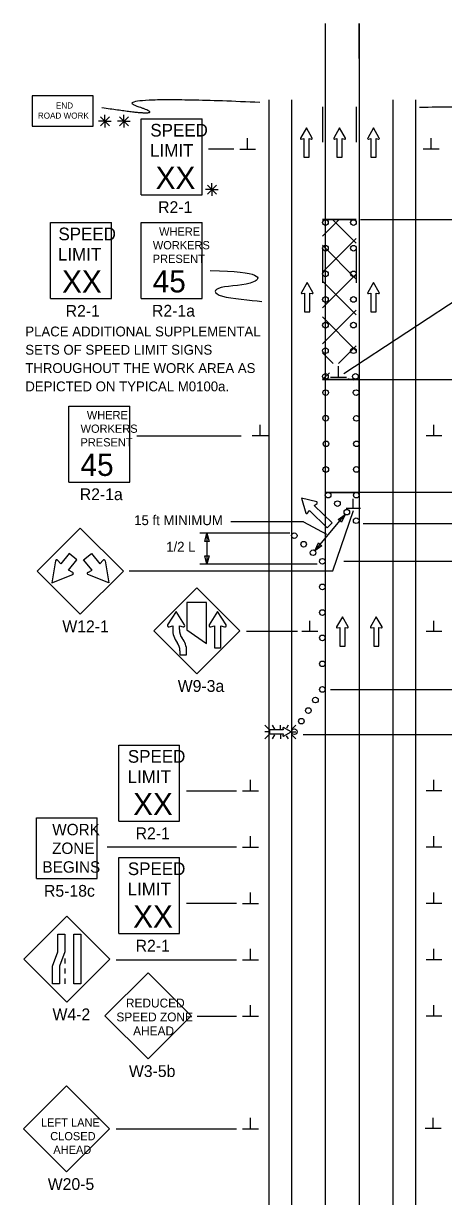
# Model space of a CAD drawing. Extents: x 16730 to 18482, y 5650 to 6977.
# Drawn here: x 16730 to 17028, y 6143 to 6977 of the extents above; entities that cross this region are included whole.
import ezdxf

# ---------------------------------------------------------------- set-up
doc = ezdxf.new("R2010")
doc.units = 0
for name, color, linetype in [('ALI_LEGAL_EX', 7, 'Continuous'), ('MT_SCRATCH_LEVEL_E', 7, 'Continuous'), ('PAVT_EDGE_EX', 7, 'Continuous'), ('TRAFFIC_SIGNS_PR', 7, 'Continuous'), ('TYPICAL_TEXT_DIMEN_PR', 7, 'Continuous')]:
    doc.layers.add(name, color=color, linetype=linetype)

msp = doc.modelspace()

# ---------------------------------------------------------------- linework, layer by layer
at = {"layer": 'ALI_LEGAL_EX'}
for p, q in [((16943.88, 6976.55), (16943.88, 6158.41)), ((16967.88, 6976.55), (16967.88, 6158.41)), ((16943.88, 6924.64), (16943.88, 6060.73)), ((16967.88, 6924.64), (16967.88, 6060.73))]:
    msp.add_line(p, q, dxfattribs=at)
for points in [[(16967.88, 6951.55), (16967.88, 6976.55)], [(16941.89, 6917.27), (16941.89, 6892.27)], [(16941.89, 6917.27), (16941.89, 6892.27)], [(16941.89, 6917.27), (16941.89, 6892.27)], [(16941.89, 6917.27), (16941.89, 6892.27)], [(16941.89, 6917.27), (16941.89, 6892.27)], [(16965.89, 6917.27), (16965.89, 6892.27)], [(16965.89, 6917.27), (16965.89, 6892.27)], [(16965.89, 6917.27), (16965.89, 6892.27)], [(16965.89, 6917.27), (16965.89, 6892.27)], [(16965.89, 6917.27), (16965.89, 6892.27)], [(16941.89, 6817.27), (16941.89, 6792.27)], [(16941.89, 6817.27), (16941.89, 6792.27)], [(16941.89, 6817.27), (16941.89, 6792.27)], [(16941.89, 6817.27), (16941.89, 6792.27)], [(16941.89, 6817.27), (16941.89, 6792.27)], [(16965.89, 6817.27), (16965.89, 6792.27)], [(16965.89, 6817.27), (16965.89, 6792.27)], [(16965.89, 6817.27), (16965.89, 6792.27)], [(16965.89, 6817.27), (16965.89, 6792.27)], [(16965.89, 6817.27), (16965.89, 6792.27)], [(16943.88, 6669.35), (16943.88, 6644.35)], [(16943.88, 6669.35), (16943.88, 6644.35)], [(16943.88, 6669.35), (16943.88, 6644.35)], [(16943.88, 6669.35), (16943.88, 6644.35)], [(16943.88, 6669.35), (16943.88, 6644.35)], [(16967.88, 6669.35), (16967.88, 6643.51)], [(16967.88, 6669.35), (16967.88, 6644.35)], [(16967.88, 6669.35), (16967.88, 6644.35)], [(16967.88, 6669.35), (16967.88, 6644.35)], [(16967.88, 6669.35), (16967.88, 6644.35)], [(16967.88, 6587.41), (16967.88, 6562.41)], [(16943.88, 6569.35), (16943.88, 6544.35)], [(16943.88, 6569.35), (16943.88, 6544.35)], [(16943.88, 6569.35), (16943.88, 6544.35)], [(16943.88, 6569.35), (16943.88, 6544.35)], [(16943.88, 6569.35), (16943.88, 6544.35)], [(16967.88, 6569.35), (16967.88, 6544.35)], [(16967.88, 6569.35), (16967.88, 6544.35)], [(16967.88, 6569.35), (16967.88, 6544.35)], [(16967.88, 6569.35), (16967.88, 6544.35)], [(16943.88, 6487.41), (16943.88, 6462.41)], [(16967.88, 6487.41), (16967.88, 6462.41)], [(16943.88, 6469.35), (16943.88, 6444.35)], [(16943.88, 6469.35), (16943.88, 6444.35)], [(16943.88, 6469.35), (16943.88, 6444.35)], [(16943.88, 6469.35), (16943.88, 6444.35)], [(16967.88, 6469.35), (16967.88, 6444.35)], [(16967.88, 6469.35), (16967.88, 6444.35)], [(16967.88, 6469.35), (16967.88, 6444.35)], [(16967.88, 6469.35), (16967.88, 6444.35)], [(16943.88, 6387.41), (16943.88, 6362.41)], [(16967.88, 6387.41), (16967.88, 6362.41)], [(16943.88, 6369.35), (16943.88, 6344.35)], [(16943.88, 6369.35), (16943.88, 6344.35)], [(16943.88, 6369.35), (16943.88, 6344.35)], [(16943.88, 6369.35), (16943.88, 6344.35)], [(16967.88, 6369.35), (16967.88, 6344.35)], [(16967.88, 6369.35), (16967.88, 6344.35)], [(16967.88, 6369.35), (16967.88, 6344.35)], [(16967.88, 6369.35), (16967.88, 6344.35)], [(16943.88, 6287.41), (16943.88, 6262.41)], [(16967.88, 6287.41), (16967.88, 6262.41)], [(16943.88, 6269.35), (16943.88, 6244.35)], [(16943.88, 6269.35), (16943.88, 6244.35)], [(16943.88, 6269.35), (16943.88, 6244.35)], [(16943.88, 6269.35), (16943.88, 6244.35)], [(16967.88, 6269.35), (16967.88, 6244.35)], [(16967.88, 6269.35), (16967.88, 6244.35)], [(16967.88, 6269.35), (16967.88, 6244.35)], [(16967.88, 6269.35), (16967.88, 6244.35)], [(16943.88, 6187.41), (16943.88, 6162.41)], [(16967.88, 6187.41), (16967.88, 6162.41)], [(16943.88, 6169.35), (16943.88, 6144.35)], [(16943.88, 6169.35), (16943.88, 6144.35)], [(16943.88, 6169.35), (16943.88, 6144.35)], [(16967.88, 6169.35), (16967.88, 6144.35)], [(16967.88, 6169.35), (16967.88, 6144.35)], [(16967.88, 6169.35), (16967.88, 6144.35)], [(16967.88, 6169.35), (16967.88, 6144.35)]]:
    msp.add_lwpolyline(points, dxfattribs=at)
at = {"layer": 'MT_SCRATCH_LEVEL_E'}
for p, q in [((16930.45, 6902.35), (16926.34, 6895.11)), ((16934.59, 6895.11), (16930.45, 6902.35)), ((16953.99, 6902.35), (16949.88, 6895.11)), ((16958.14, 6895.11), (16953.99, 6902.35)), ((16978.06, 6902.35), (16973.95, 6895.11)), ((16982.21, 6895.11), (16978.06, 6902.35)), ((16926.82, 6894.42), (16928.59, 6894.74)), ((16928.59, 6894.74), (16928.59, 6881.48)), ((16932.34, 6881.48), (16932.34, 6894.74)), ((16932.34, 6894.74), (16934.11, 6894.42)), ((16950.36, 6894.42), (16952.14, 6894.74)), ((16952.14, 6894.74), (16952.14, 6881.48)), ((16955.88, 6881.48), (16955.88, 6894.74)), ((16955.88, 6894.74), (16957.66, 6894.42)), ((16974.44, 6894.42), (16976.21, 6894.74)), ((16976.21, 6894.74), (16976.21, 6881.48)), ((16979.95, 6881.48), (16979.95, 6894.74)), ((16979.95, 6894.74), (16981.73, 6894.42)), ((16928.59, 6881.48), (16932.34, 6881.48)), ((16952.14, 6881.48), (16955.88, 6881.48)), ((16976.21, 6881.48), (16979.95, 6881.48)), ((16930.98, 6792.54), (16926.87, 6785.3)), ((16935.12, 6785.3), (16930.98, 6792.54)), ((16978.06, 6792.54), (16973.95, 6785.3)), ((16982.21, 6785.3), (16978.06, 6792.54)), ((16927.35, 6784.61), (16929.12, 6784.93)), ((16929.12, 6784.93), (16929.12, 6771.67)), ((16932.87, 6771.67), (16932.87, 6784.93)), ((16932.87, 6784.93), (16934.64, 6784.61)), ((16974.44, 6784.61), (16976.21, 6784.93)), ((16976.21, 6784.93), (16976.21, 6771.67)), ((16979.95, 6771.67), (16979.95, 6784.93)), ((16979.95, 6784.93), (16981.73, 6784.61)), ((16929.12, 6771.67), (16932.87, 6771.67)), ((16976.21, 6771.67), (16979.95, 6771.67)), ((16937.78, 6636.61), (16927, 6639.37)), ((16927, 6639.37), (16930.11, 6628.71)), ((16936.03, 6634.1), (16937.99, 6635.51)), ((16948.71, 6621.79), (16936.03, 6634.1)), ((16931.21, 6628.53), (16932.56, 6630.53)), ((16932.56, 6630.53), (16945.24, 6618.21)), ((16945.24, 6618.21), (16948.71, 6621.79)), ((16955.98, 6555.06), (16951.87, 6547.82)), ((16960.13, 6547.82), (16955.98, 6555.06)), ((16980.06, 6555.06), (16975.94, 6547.82)), ((16984.2, 6547.82), (16980.06, 6555.06)), ((16952.36, 6547.13), (16954.13, 6547.45)), ((16954.13, 6547.45), (16954.13, 6534.19)), ((16957.87, 6534.19), (16957.87, 6547.45)), ((16957.87, 6547.45), (16959.65, 6547.13)), ((16976.43, 6547.13), (16978.2, 6547.45)), ((16978.2, 6547.45), (16978.2, 6534.19)), ((16981.95, 6534.19), (16981.95, 6547.45)), ((16981.95, 6547.45), (16983.72, 6547.13)), ((16954.13, 6534.19), (16957.87, 6534.19)), ((16978.2, 6534.19), (16981.95, 6534.19))]:
    msp.add_line(p, q, dxfattribs=at)
for centre, radius, start, end in [((16926.74, 6894.88), 0.463, 150.42484, 279.96381), ((16934.18, 6894.88), 0.463, 260.03619, 29.77312), ((16950.29, 6894.88), 0.463, 150.42484, 279.96381), ((16957.73, 6894.88), 0.463, 260.03619, 29.77312), ((16974.36, 6894.88), 0.463, 150.42484, 279.96381), ((16981.8, 6894.88), 0.463, 260.03619, 29.77312), ((16927.27, 6785.07), 0.463, 150.42484, 279.96381), ((16934.71, 6785.07), 0.463, 260.03619, 29.77312), ((16974.36, 6785.07), 0.463, 150.42484, 279.96381), ((16981.8, 6785.07), 0.463, 260.03619, 29.77312), ((16937.61, 6636), 0.617, 305.86459, 75.60151), ((16930.7, 6628.89), 0.617, 196.25324, 325.7922), ((16952.28, 6547.59), 0.463, 150.42484, 279.96381), ((16959.72, 6547.59), 0.463, 260.03619, 29.77312), ((16976.35, 6547.59), 0.463, 150.42484, 279.96381), ((16983.79, 6547.59), 0.463, 260.03619, 29.77312)]:
    msp.add_arc(centre, radius, start, end, dxfattribs=at)
at = {"layer": 'PAVT_EDGE_EX'}
for p, q in [((16903.88, 6922.29), (16903.88, 6020.63)), ((16919.88, 6922.29), (16919.88, 6020.63)), ((16991.88, 6922.29), (16991.88, 6020.63)), ((17007.88, 6922.29), (17007.88, 6020.63)), ((16965.89, 6837.23), (16941.89, 6837.23)), ((16941.89, 6837.23), (16965.89, 6837.23)), ((16941.89, 6837.23), (16965.89, 6837.23)), ((16941.89, 6825.33), (16953.79, 6837.23)), ((16965.89, 6820.42), (16949.08, 6837.23)), ((16941.89, 6799.87), (16965.89, 6823.87)), ((16965.89, 6794.97), (16941.89, 6818.97)), ((16941.89, 6774.42), (16965.89, 6798.42)), ((16965.89, 6769.51), (16941.89, 6793.51)), ((16941.89, 6748.96), (16965.89, 6772.96)), ((16965.89, 6744.05), (16941.89, 6768.05)), ((16949.55, 6734.93), (16941.89, 6742.6)), ((16953.23, 6734.85), (16965.89, 6747.51)), ((16941.89, 6723.51), (16946.75, 6728.37)), ((16941.89, 6723.51), (16965.89, 6723.51)), ((16941.89, 6723.51), (16965.89, 6723.51)), ((16965.89, 6723.51), (16941.89, 6723.51)), ((16941.89, 6723.51), (16941.89, 6723.51)), ((16942.81, 6723.15), (16942.87, 6723.26)), ((16949.7, 6723.15), (16949.75, 6723.26)), ((16956.59, 6723.15), (16956.64, 6723.26)), ((16960.98, 6723.51), (16960.32, 6724.17)), ((16963.48, 6723.15), (16963.53, 6723.26)), ((16943.88, 6643.52), (16967.88, 6643.52))]:
    msp.add_line(p, q, dxfattribs=at)
msp.add_lwpolyline([(16967.84, 6723.45), (16943.86, 6723.45), (16943.86, 6643.4), (16967.84, 6643.4)], close=True, dxfattribs=at)
at = {"layer": 'TRAFFIC_SIGNS_PR'}
for p, q in [((16813.23, 6908.75), (16856.43, 6908.75)), ((16813.23, 6854.75), (16813.23, 6908.75)), ((16856.43, 6854.75), (16856.43, 6908.75)), ((16813.23, 6854.75), (16856.43, 6854.75)), ((16748.85, 6835.03), (16792.05, 6835.03)), ((16748.85, 6781.03), (16748.85, 6835.03)), ((16792.05, 6781.03), (16792.05, 6835.03)), ((16813.19, 6835.13), (16856.39, 6835.13)), ((16813.19, 6781.13), (16813.19, 6835.13)), ((16856.39, 6781.13), (16856.39, 6835.13)), ((16748.85, 6781.03), (16792.05, 6781.03)), ((16813.19, 6781.13), (16856.39, 6781.13)), ((16761.94, 6704.76), (16805.14, 6704.76)), ((16761.94, 6650.76), (16761.94, 6704.76)), ((16805.14, 6650.76), (16805.14, 6704.76)), ((16761.94, 6650.76), (16805.14, 6650.76)), ((16770.02, 6618.01), (16739.47, 6587.46)), ((16800.57, 6587.46), (16770.02, 6618.01)), ((16753.24, 6594.66), (16752.38, 6594.8)), ((16739.47, 6587.46), (16770.02, 6556.91)), ((16764.28, 6585.8), (16764.61, 6584.96)), ((16770.02, 6556.91), (16800.57, 6587.46)), ((16852.76, 6575.63), (16822.21, 6545.08)), ((16883.3, 6545.08), (16852.76, 6575.63)), ((16822.21, 6545.08), (16852.76, 6514.54)), ((16852.76, 6514.54), (16883.3, 6545.08)), ((16903.9, 6475.24), (16901.08, 6478.06)), ((16906.19, 6478.06), (16907.82, 6475.24)), ((16911.98, 6475.24), (16911.98, 6478.06)), ((16917.45, 6478.06), (16916.24, 6475.97)), ((16922.89, 6478.06), (16920.07, 6475.24)), ((16903.9, 6473.21), (16901.08, 6473.21)), ((16903.9, 6471.17), (16901.08, 6468.35)), ((16907.85, 6471.17), (16906.22, 6468.35)), ((16911.98, 6471.17), (16911.98, 6468.35)), ((16916.17, 6470.54), (16917.43, 6468.35)), ((16920.07, 6473.21), (16922.89, 6473.21)), ((16922.89, 6468.36), (16920.07, 6471.17)), ((16797.28, 6463.86), (16840.48, 6463.86)), ((16797.28, 6409.86), (16797.28, 6463.86)), ((16840.48, 6409.86), (16840.48, 6463.86)), ((16738.86, 6368.99), (16738.86, 6412.19)), ((16738.86, 6412.19), (16782.06, 6412.19)), ((16782.06, 6368.99), (16782.06, 6412.19)), ((16797.28, 6409.86), (16840.48, 6409.86)), ((16797.28, 6384.03), (16840.48, 6384.03)), ((16797.28, 6330.03), (16797.28, 6384.03)), ((16840.48, 6330.03), (16840.48, 6384.03)), ((16738.86, 6368.99), (16782.06, 6368.99)), ((16760.49, 6342.33), (16729.94, 6311.78)), ((16791.03, 6311.78), (16760.49, 6342.33)), ((16797.28, 6330.03), (16840.48, 6330.03)), ((16729.94, 6311.78), (16760.49, 6281.23)), ((16759.08, 6312.33), (16759.08, 6308.73)), ((16760.49, 6281.23), (16791.03, 6311.78)), ((16759.08, 6305.13), (16759.08, 6301.53)), ((16818.08, 6302.02), (16787.54, 6271.48)), ((16848.63, 6271.48), (16818.08, 6302.02)), ((16759.08, 6297.93), (16759.08, 6294.33)), ((16787.54, 6271.48), (16818.08, 6240.93)), ((16818.08, 6240.93), (16848.63, 6271.48)), ((16760.25, 6221.75), (16729.7, 6191.2)), ((16790.8, 6191.2), (16760.25, 6221.75)), ((16729.7, 6191.2), (16760.25, 6160.65)), ((16760.25, 6160.65), (16790.8, 6191.2))]:
    msp.add_line(p, q, dxfattribs=at)
for points in [[(16735.84, 6903.59), (16779.04, 6903.59), (16779.04, 6925.19), (16735.84, 6925.19)], [(16845.66, 6565.26), (16845.66, 6545.74), (16859.61, 6536.05), (16859.61, 6565.26)], [(16759.08, 6329.48), (16759.08, 6316.9), (16755.32, 6306.91), (16755.32, 6294.33), (16750.27, 6294.33), (16750.27, 6306.91), (16754.03, 6316.9), (16754.03, 6329.48)], [(16770.49, 6329.48), (16770.49, 6294.33), (16765.43, 6294.33), (16765.43, 6329.48)]]:
    msp.add_lwpolyline(points, close=True, dxfattribs=at)
for points in [[(16752.38, 6594.8), (16749.84, 6579.18), (16764.61, 6584.96)], [(16764.71, 6586.59), (16761.7, 6588.2), (16767.64, 6595.57), (16762.09, 6600.03), (16756.16, 6592.65), (16753.91, 6595.24)], [(16775.32, 6586.59), (16778.33, 6588.2), (16772.4, 6595.57), (16777.94, 6600.03), (16783.88, 6592.65), (16786.13, 6595.24)], [(16787.66, 6594.8), (16790.2, 6579.18), (16775.43, 6584.96)], [(16843.97, 6549.25), (16837.98, 6558.67), (16831.99, 6549.25)], [(16873.48, 6549.25), (16867.49, 6558.67), (16861.49, 6549.25)], [(16833.03, 6547.83), (16835.62, 6548.54), (16835.61, 6546.03)], [(16840.33, 6545.92), (16840.34, 6548.54), (16842.92, 6547.83)], [(16862.54, 6547.83), (16865.13, 6548.54), (16865.13, 6533.02), (16869.85, 6533.02), (16869.85, 6548.54), (16872.43, 6547.83)], [(16840.75, 6530.9), (16840.75, 6527.92), (16845.47, 6527.92), (16845.47, 6530.9)], [(16913.81, 6475.89), (16914.04, 6474.59), (16904.32, 6474.59), (16904.32, 6471.85), (16914.04, 6471.85), (16913.81, 6470.55)], [(16914.31, 6470.19), (16919.62, 6473.21), (16914.31, 6476.25)]]:
    msp.add_lwpolyline(points, dxfattribs=at)
for centre in [(16943.99, 6835.11), (16963.86, 6835.11), (16943.99, 6816.89), (16963.86, 6816.89), (16943.99, 6798.68), (16963.86, 6798.68), (16943.99, 6780.47), (16963.86, 6780.47), (16943.99, 6762.25), (16963.86, 6762.25), (16943.99, 6744.04), (16963.86, 6744.04), (16943.99, 6725.82), (16965.28, 6725.82), (16944.09, 6714.29), (16965.72, 6714.29), (16944.09, 6696.09), (16965.96, 6695.97), (16944.33, 6677.89), (16965.97, 6677.89), (16944.22, 6659.69), (16965.85, 6659.69), (16945.86, 6641.48), (16965.85, 6641.47), (16952.51, 6635.42), (16959.16, 6629.35), (16965.81, 6623.28), (16921.87, 6612.65), (16928.52, 6606.59), (16935.17, 6600.52), (16941.81, 6594.45), (16941.81, 6594.45), (16941.81, 6576.24), (16941.81, 6558.03), (16941.81, 6540.03), (16941.81, 6521.6), (16941.81, 6503.38), (16936.85, 6495.87), (16931.88, 6488.37), (16926.91, 6480.86), (16921.94, 6473.36)]:
    msp.add_circle(centre, 2, dxfattribs=at)
for centre, radius, start, end in [((16753.25, 6594.65), 0.885, 41.8659, 170.0393), ((16786.79, 6594.65), 0.885, 9.9607, 138.1341), ((16764.28, 6585.8), 0.9, 291.40774, 61.17916), ((16775.76, 6585.8), 0.9, 118.82084, 248.59226), ((16832.78, 6548.74), 0.945, 147.52044, 285.3986), ((16849.78, 6545.62), 14.17, 178.32933, 218.54273), ((16828.53, 6546.29), 11.81, 358.18937, 0.00483), ((16849.78, 6545.62), 9.45, 178.19356, 218.54646), ((16843.17, 6548.75), 0.947, 254.68281, 32.2708), ((16839.8, 6536.44), 11.81, 74.67996, 74.68078), ((16853.94, 6555.59), 11.81, 212.45689, 212.46649), ((16862.29, 6548.74), 0.946, 147.54971, 285.33159), ((16872.68, 6548.74), 0.943, 254.67777, 32.46648), ((16883.44, 6555.59), 11.81, 212.45689, 212.46649), ((16831.3, 6530.9), 9.45, 0, 38.54567), ((16831.3, 6530.9), 14.17, 0, 38.5422), ((16914.14, 6475.95), 0.341, 61.48329, 189.95933), ((16914.14, 6470.49), 0.341, 170.73078, 298.89165)]:
    msp.add_arc(centre, radius, start, end, dxfattribs=at)
for points in [[(16785.38, 6916.88), (16835.79, 6909.06), (16786.61, 6925.59), (16897.4, 6920.65)], [(17126.47, 6908.26), (17060.05, 6907.48), (17118.8, 6918.29), (17010.82, 6916.87)]]:
    msp.add_open_spline(points, degree=2, dxfattribs=at)
at = {"layer": 'TYPICAL_TEXT_DIMEN_PR'}
for p, q in [((16784.29, 6910.26), (16790.66, 6903.89)), ((16790.66, 6910.26), (16784.29, 6903.89)), ((16787.48, 6907.08), (16787.48, 6911.53)), ((16797.8, 6910.26), (16804.17, 6903.89)), ((16804.17, 6910.26), (16797.8, 6903.89)), ((16800.98, 6907.08), (16800.98, 6911.53)), ((16787.48, 6907.08), (16782.94, 6907.08)), ((16787.48, 6907.08), (16790.66, 6907.08)), ((16787.48, 6907.08), (16791.95, 6907.08)), ((16787.48, 6907.08), (16787.48, 6902.58)), ((16800.98, 6907.08), (16796.45, 6907.08)), ((16800.98, 6907.08), (16804.17, 6907.08)), ((16800.98, 6907.08), (16805.46, 6907.08)), ((16800.98, 6907.08), (16800.98, 6902.58)), ((16888.76, 6887.23), (16888.76, 6895.02)), ((17208.35, 6893.17), (16957.07, 6727.68)), ((17019.01, 6887.23), (17019.01, 6895.02)), ((16878.89, 6887.23), (16860.99, 6887.23)), ((16883.14, 6887.23), (16894.39, 6887.23)), ((17024.64, 6887.23), (17013.39, 6887.23)), ((16860.26, 6861.7), (16866.63, 6855.32)), ((16866.63, 6861.7), (16860.26, 6855.32)), ((16863.45, 6858.51), (16863.45, 6862.97)), ((16863.45, 6858.51), (16858.91, 6858.51)), ((16863.45, 6858.51), (16866.63, 6858.51)), ((16863.45, 6858.51), (16867.92, 6858.51)), ((16863.45, 6858.51), (16863.45, 6854.01)), ((16968.82, 6837.23), (17054.89, 6837.23)), ((16953.29, 6725.19), (16953.29, 6732.98)), ((16947.67, 6725.19), (16958.92, 6725.19)), ((16965.89, 6723.51), (17054.89, 6723.51)), ((16897.68, 6683.51), (16897.68, 6691.3)), ((17021, 6683.51), (17021, 6691.3)), ((16810.2, 6683.51), (16884.06, 6683.51)), ((16903.3, 6683.51), (16892.05, 6683.51)), ((17026.63, 6683.51), (17015.38, 6683.51)), ((16967.88, 6643.51), (17056.88, 6643.51)), ((16963.71, 6631.92), (16963.71, 6638.92)), ((16936.55, 6601.97), (16957.99, 6627.73)), ((16949.16, 6587.73), (16963.96, 6630.47)), ((16953.03, 6624.23), (16957.99, 6627.73)), ((16957.99, 6627.73), (16955.44, 6622.22)), ((16968.77, 6631.92), (16958.64, 6631.92)), ((16928.39, 6622.5), (16876.92, 6622.5)), ((16928.39, 6622.5), (16944.8, 6613.67)), ((16954.24, 6623.23), (16953.03, 6624.23)), ((16955.44, 6622.22), (16954.24, 6623.23)), ((16970.81, 6621.26), (17091.69, 6621.26)), ((16918.6, 6614.43), (16854.88, 6614.43)), ((16858.31, 6608.57), (16859.88, 6614.43)), ((16859.88, 6614.43), (16861.45, 6608.57)), ((16859.88, 6614.43), (16859.88, 6592.45)), ((16859.88, 6608.57), (16858.31, 6608.57)), ((16861.45, 6608.57), (16859.88, 6608.57)), ((16936.55, 6601.97), (16939.09, 6607.48)), ((16941.5, 6605.47), (16936.55, 6601.97)), ((16939.09, 6607.48), (16940.3, 6606.48)), ((16940.3, 6606.48), (16941.5, 6605.47)), ((16938.05, 6592.45), (16854.88, 6592.45)), ((16859.88, 6592.45), (16858.31, 6598.32)), ((16858.31, 6598.32), (16859.88, 6598.32)), ((16859.88, 6598.32), (16861.45, 6598.32)), ((16861.45, 6598.32), (16859.88, 6592.45)), ((16957.13, 6594.45), (17056.88, 6594.45)), ((16804.81, 6587.73), (16949.16, 6587.73)), ((16932.92, 6544.45), (16932.92, 6552.24)), ((17021, 6544.45), (17021, 6552.24)), ((16924.09, 6544.45), (16888.03, 6544.45)), ((16938.54, 6544.45), (16927.29, 6544.45)), ((17026.63, 6544.45), (17015.38, 6544.45)), ((16947.63, 6503.38), (17091.69, 6503.38)), ((16928.28, 6471.28), (17056.88, 6471.28)), ((16890.75, 6431.28), (16890.75, 6439.06)), ((17021, 6431.28), (17021, 6439.06)), ((16845.28, 6431.28), (16880.88, 6431.28)), ((16885.13, 6431.28), (16896.38, 6431.28)), ((17026.63, 6431.28), (17015.38, 6431.28)), ((16890.75, 6391.28), (16890.75, 6399.06)), ((17021, 6391.28), (17021, 6399.06)), ((16880.88, 6391.28), (16789.06, 6391.28)), ((16885.13, 6391.28), (16896.38, 6391.28)), ((17026.63, 6391.28), (17015.38, 6391.28)), ((16890.75, 6351.28), (16890.75, 6359.06)), ((17021, 6351.28), (17021, 6359.06)), ((16880.88, 6351.28), (16845.28, 6351.28)), ((16885.13, 6351.28), (16896.38, 6351.28)), ((17026.63, 6351.28), (17015.38, 6351.28)), ((16890.75, 6311.28), (16890.75, 6319.06)), ((17021, 6311.28), (17021, 6319.06)), ((16795.52, 6311.28), (16880.88, 6311.28)), ((16885.13, 6311.28), (16896.38, 6311.28)), ((17026.63, 6311.28), (17015.38, 6311.28)), ((16890.75, 6271.28), (16890.75, 6279.06)), ((17021, 6271.28), (17021, 6279.06)), ((16853.02, 6271.28), (16880.88, 6271.28)), ((16885.13, 6271.28), (16896.38, 6271.28)), ((17026.63, 6271.28), (17015.38, 6271.28)), ((16890.75, 6191.28), (16890.75, 6199.06)), ((17020.38, 6191.37), (17020.38, 6199.15)), ((16795.52, 6191.28), (16880.88, 6191.28)), ((16885.13, 6191.28), (16896.38, 6191.28)), ((17026, 6191.37), (17014.75, 6191.37))]:
    msp.add_line(p, q, dxfattribs=at)
for points, degree in [([(16840.62, 6870.93), (16840.63, 6870.93), (16840.64, 6870.93), (16840.64, 6870.93)], 2), ([(16862.23, 6801.04), (16899.13, 6800.6), (16898.64, 6790.32), (16864.23, 6790.32), (16864.23, 6781.89), (16890.68, 6779.98), (16898.83, 6779.13)], 3)]:
    msp.add_open_spline(points, degree=degree, dxfattribs=at)

# ---------------------------------------------------------------- texts
at = {"layer": 'TRAFFIC_SIGNS_PR'}
for s, height, p in [('END', 4.31, (16752.71, 6916.11)), ('ROAD WORK', 4.31, (16739.9, 6908.93)), ('SPEED', 9, (16819.72, 6896.22)), ('LIMIT', 9, (16819.54, 6881.82)), ('XX', 15.785, (16823.49, 6858.98)), ('R2-1', 8.37, (16825.24, 6841.88)), ('SPEED', 9, (16754.51, 6822.5)), ('WHERE', 5.85, (16825.92, 6825.77)), ('WORKERS', 5.85, (16821.5, 6816.1)), ('LIMIT', 9, (16754.14, 6808.1)), ('PRESENT', 5.85, (16821.42, 6806.42)), ('XX', 15.785, (16757.07, 6785.26)), ('45', 15.785, (16821.41, 6785.47)), ('R2-1', 8.37, (16759.66, 6768.16)), ('R2-1a', 8.37, (16820.9, 6768.26)), ('PLACE ADDITIONAL SUPPLEMENTAL', 7, (16731, 6754.21)), ('SETS OF SPEED LIMIT SIGNS', 7, (16731, 6741.21)), ('THROUGHOUT THE WORK AREA AS', 7, (16731, 6728.21)), ('DEPICTED ON TYPICAL M0100a.', 7, (16731, 6715.21)), ('WHERE', 5.85, (16774.66, 6695.41)), ('WORKERS', 5.85, (16770.24, 6685.73)), ('PRESENT', 5.85, (16770.17, 6676.06)), ('45', 15.785, (16770.15, 6655.1)), ('R2-1a', 8.37, (16769.65, 6637.89)), ('W12-1', 8.37, (16757.28, 6544.04)), ('W9-3a', 8.37, (16839.19, 6501.67)), ('SPEED', 9, (16803.76, 6451.33)), ('LIMIT', 9, (16803.58, 6436.93)), ('XX', 15.785, (16807.53, 6414.09)), ('WORK', 8.119, (16750.11, 6399.78)), ('R2-1', 8.37, (16809.29, 6396.99)), ('ZONE', 8.119, (16749.97, 6386.5)), ('BEGINS', 8.119, (16743.14, 6373.21)), ('SPEED', 9, (16803.76, 6371.5)), ('R5-18c', 8.37, (16744.27, 6356.13)), ('LIMIT', 9, (16803.58, 6357.1)), ('XX', 15.785, (16807.53, 6334.26)), ('R2-1', 8.37, (16809.29, 6317.16)), ('W4-2', 8.37, (16750.31, 6268.36)), ('REDUCED', 6.3, (16802.4, 6277.45)), ('SPEED ZONE', 6.3, (16795.64, 6267.55)), ('AHEAD', 6.3, (16807.52, 6257.65)), ('W3-5b', 8.37, (16804.53, 6228.06)), ('LEFT LANE', 5.85, (16742.12, 6192.77)), ('CLOSED', 5.85, (16748.68, 6183.1)), ('AHEAD', 5.85, (16750.87, 6173.42)), ('W20-5', 8.37, (16746.94, 6147.79))]:
    msp.add_text(s, height=height, dxfattribs=at).set_placement(p)
at = {"layer": 'TYPICAL_TEXT_DIMEN_PR'}
for s, p in [('15 ft MINIMUM', (16808.24, 6620.14)), ('1/2 L', (16830.95, 6601.27))]:
    msp.add_text(s, height=7, dxfattribs=at).set_placement(p)

doc.saveas('drawing.dxf')
